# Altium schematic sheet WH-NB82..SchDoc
size 431 x 279 mm
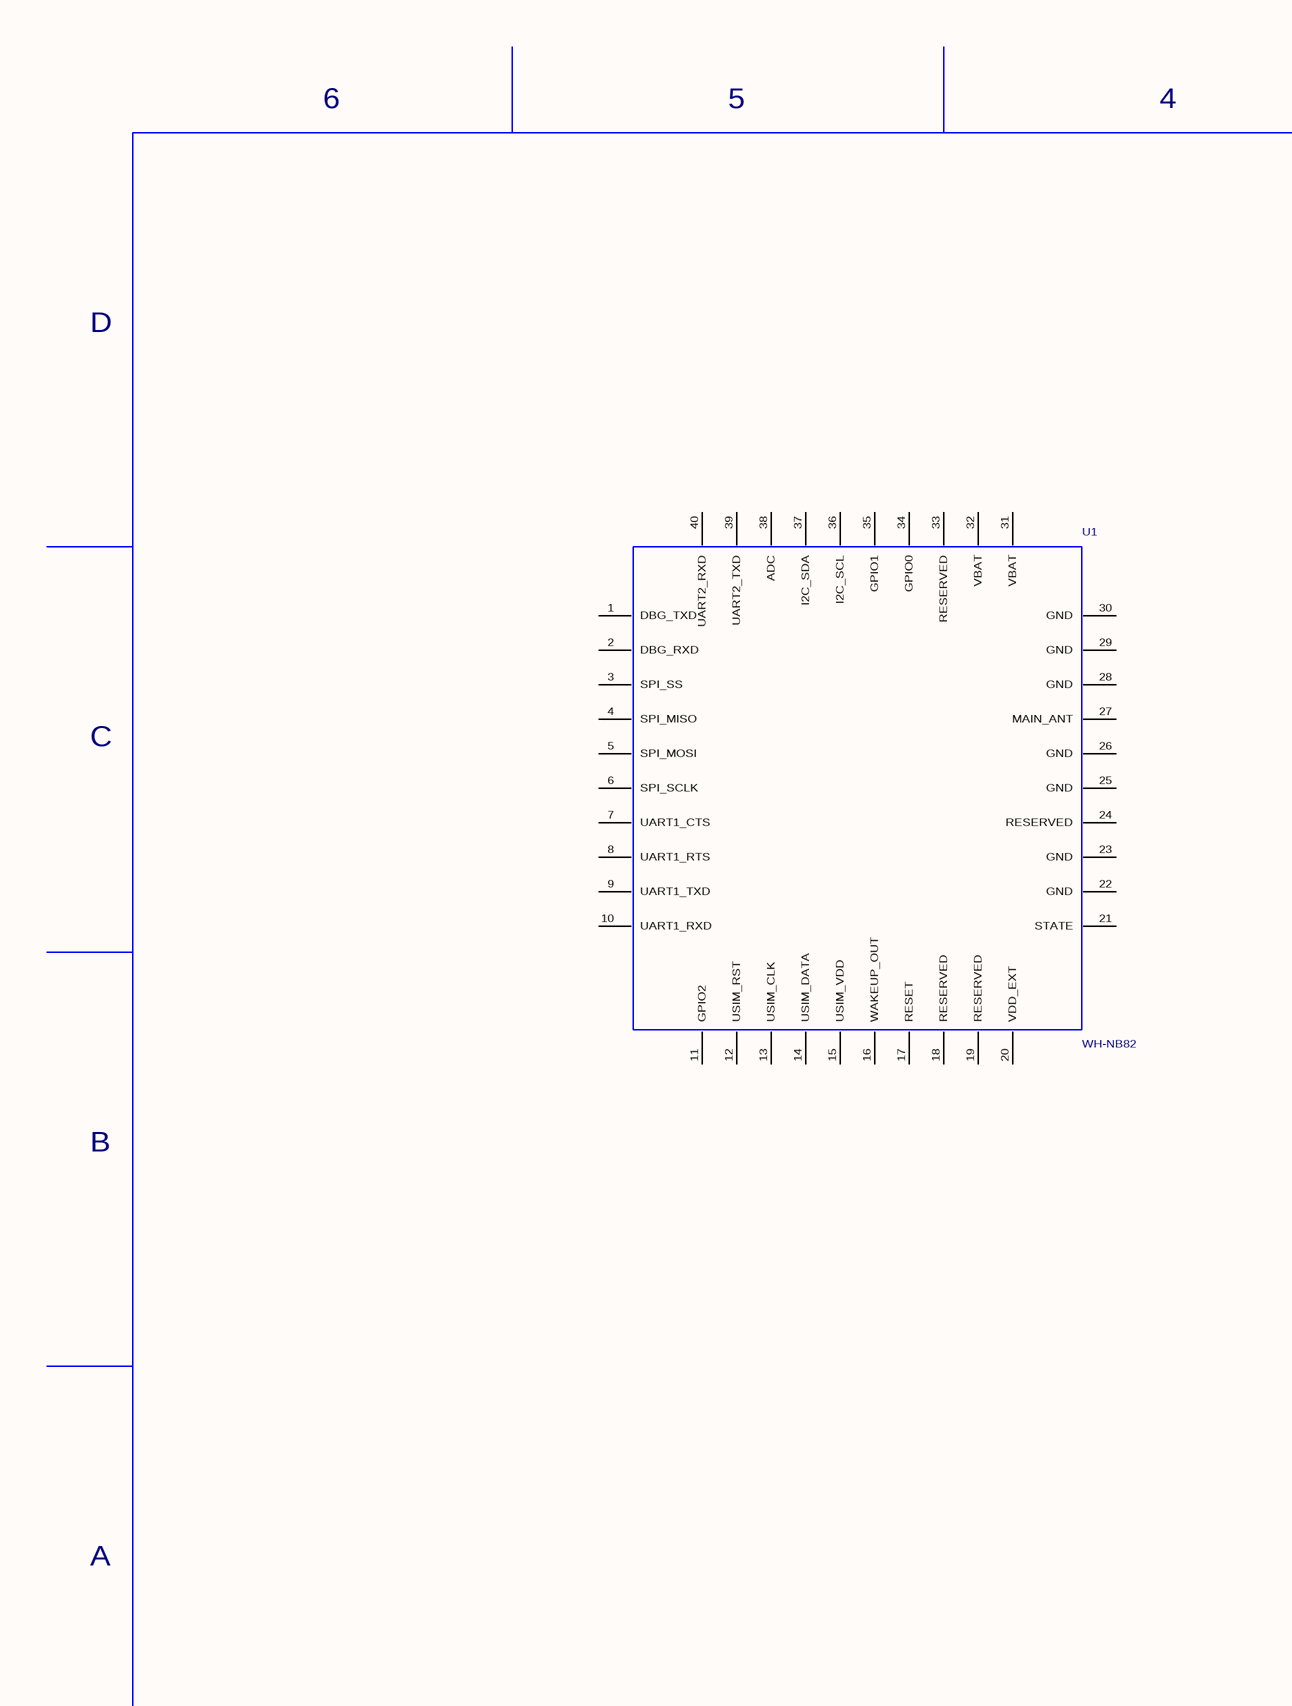
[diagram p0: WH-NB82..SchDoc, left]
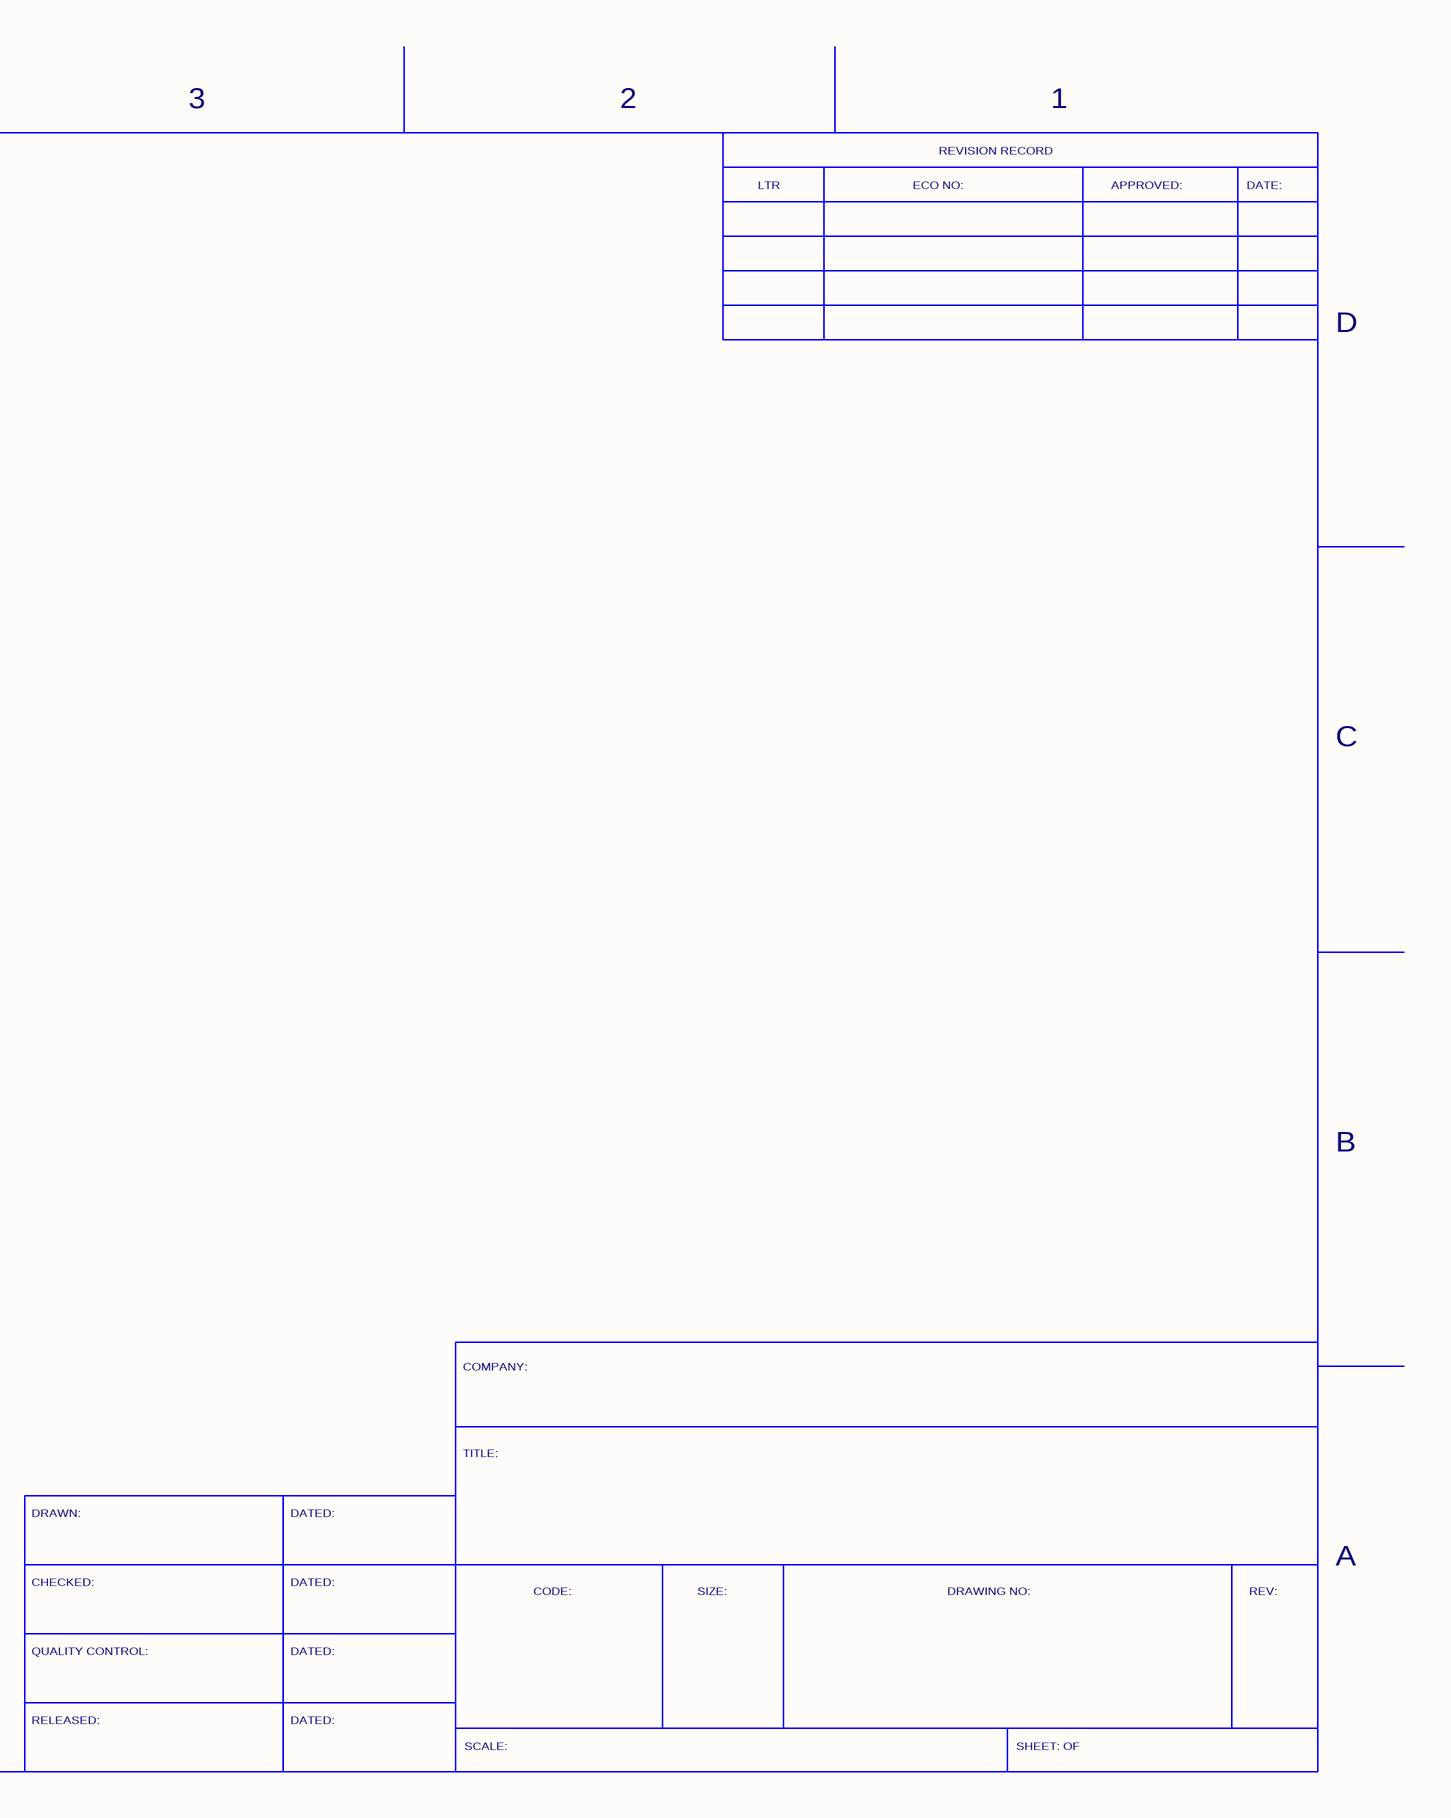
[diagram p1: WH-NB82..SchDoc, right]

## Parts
U1  WH-NB82  [WH-NB82]

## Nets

Not connected (* = marked no-connect by the designer): U1 1(DBG_TXD) 2(DBG_RXD) 3(SPI_SS) 4(SPI_MISO) 5(SPI_MOSI) 6(SPI_SCLK) 7(UART1_CTS) 8(UART1_RTS) 9(UART1_TXD) 10(UART1_RXD) 11(GPIO2) 12(USIM_RST) 13(USIM_CLK) 14(USIM_DATA) 15(USIM_VDD) 16(WAKEUP_OUT) 17(RESET) 18(RESERVED) 19(RESERVED) 20(VDD_EXT) 21(STATE) 22(GND) 23(GND) 24(RESERVED) 25(GND) 26(GND) 27(MAIN_ANT) 28(GND) 29(GND) 30(GND) 31(VBAT) 32(VBAT) 33(RESERVED) 34(GPIO0) 35(GPIO1) 36(I2C_SCL) 37(I2C_SDA) 38(ADC) 39(UART2_TXD) 40(UART2_RXD)

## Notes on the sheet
- 6
- 5
- 4
- 3
- 2
- REVISION RECORD
- 1
- LTR
- ECO NO:
- APPROVED:
- DATE:
- D
- C
- B
- COMPANY:
- TITLE:
- DRAWN:
- DATED:
- A
- CHECKED:
- CODE:
- SIZE:
- DRAWING NO:
- REV:
- QUALITY CONTROL:
- RELEASED:
- SCALE:
- SHEET: OF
